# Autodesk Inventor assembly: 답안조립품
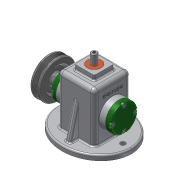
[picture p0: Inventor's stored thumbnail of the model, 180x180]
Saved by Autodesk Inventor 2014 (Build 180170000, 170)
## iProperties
Created: 2017-07
Part Number: 답안조립품
Document SubType Name: Assembly
Designer: user
Author: user
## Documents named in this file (16)
- C:\Users\user\Desktop\470708V1019\답안조립품.iam
- C:\Users\user\Desktop\470708V1019\V벨트풀리.ipt
- C:\Users\user\Desktop\470708V1019\고정핀 1.2 x  8.ipt
- C:\Users\user\Desktop\470708V1019\뒤커버.ipt
- C:\Users\user\Desktop\470708V1019\링크.ipt
- C:\Users\user\Desktop\470708V1019\멈춤나사 M3x8.ipt
- C:\Users\user\Desktop\470708V1019\베어링 12 x 32 x 10.ipt
- C:\Users\user\Desktop\470708V1019\본체.ipt
- C:\Users\user\Desktop\470708V1019\볼트 M4 x 12.ipt
- C:\Users\user\Desktop\470708V1019\부시.ipt
- C:\Users\user\Desktop\470708V1019\슬라이드.ipt
- C:\Users\user\Desktop\470708V1019\앞커버.ipt
- C:\Users\user\Desktop\470708V1019\오일실 12 25 7.ipt
- C:\Users\user\Desktop\470708V1019\키 4 x 4 x 10.ipt
- C:\Users\user\Desktop\470708V1019\편심축.ipt
- C:\Users\user\Desktop\470708V1019\핀 5 x 18.ipt
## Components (3 placed, 3 different names)
1. V벨트풀리:1
2. 고정핀 1.2 x  8:1
3. 핀 5 x 18:1
